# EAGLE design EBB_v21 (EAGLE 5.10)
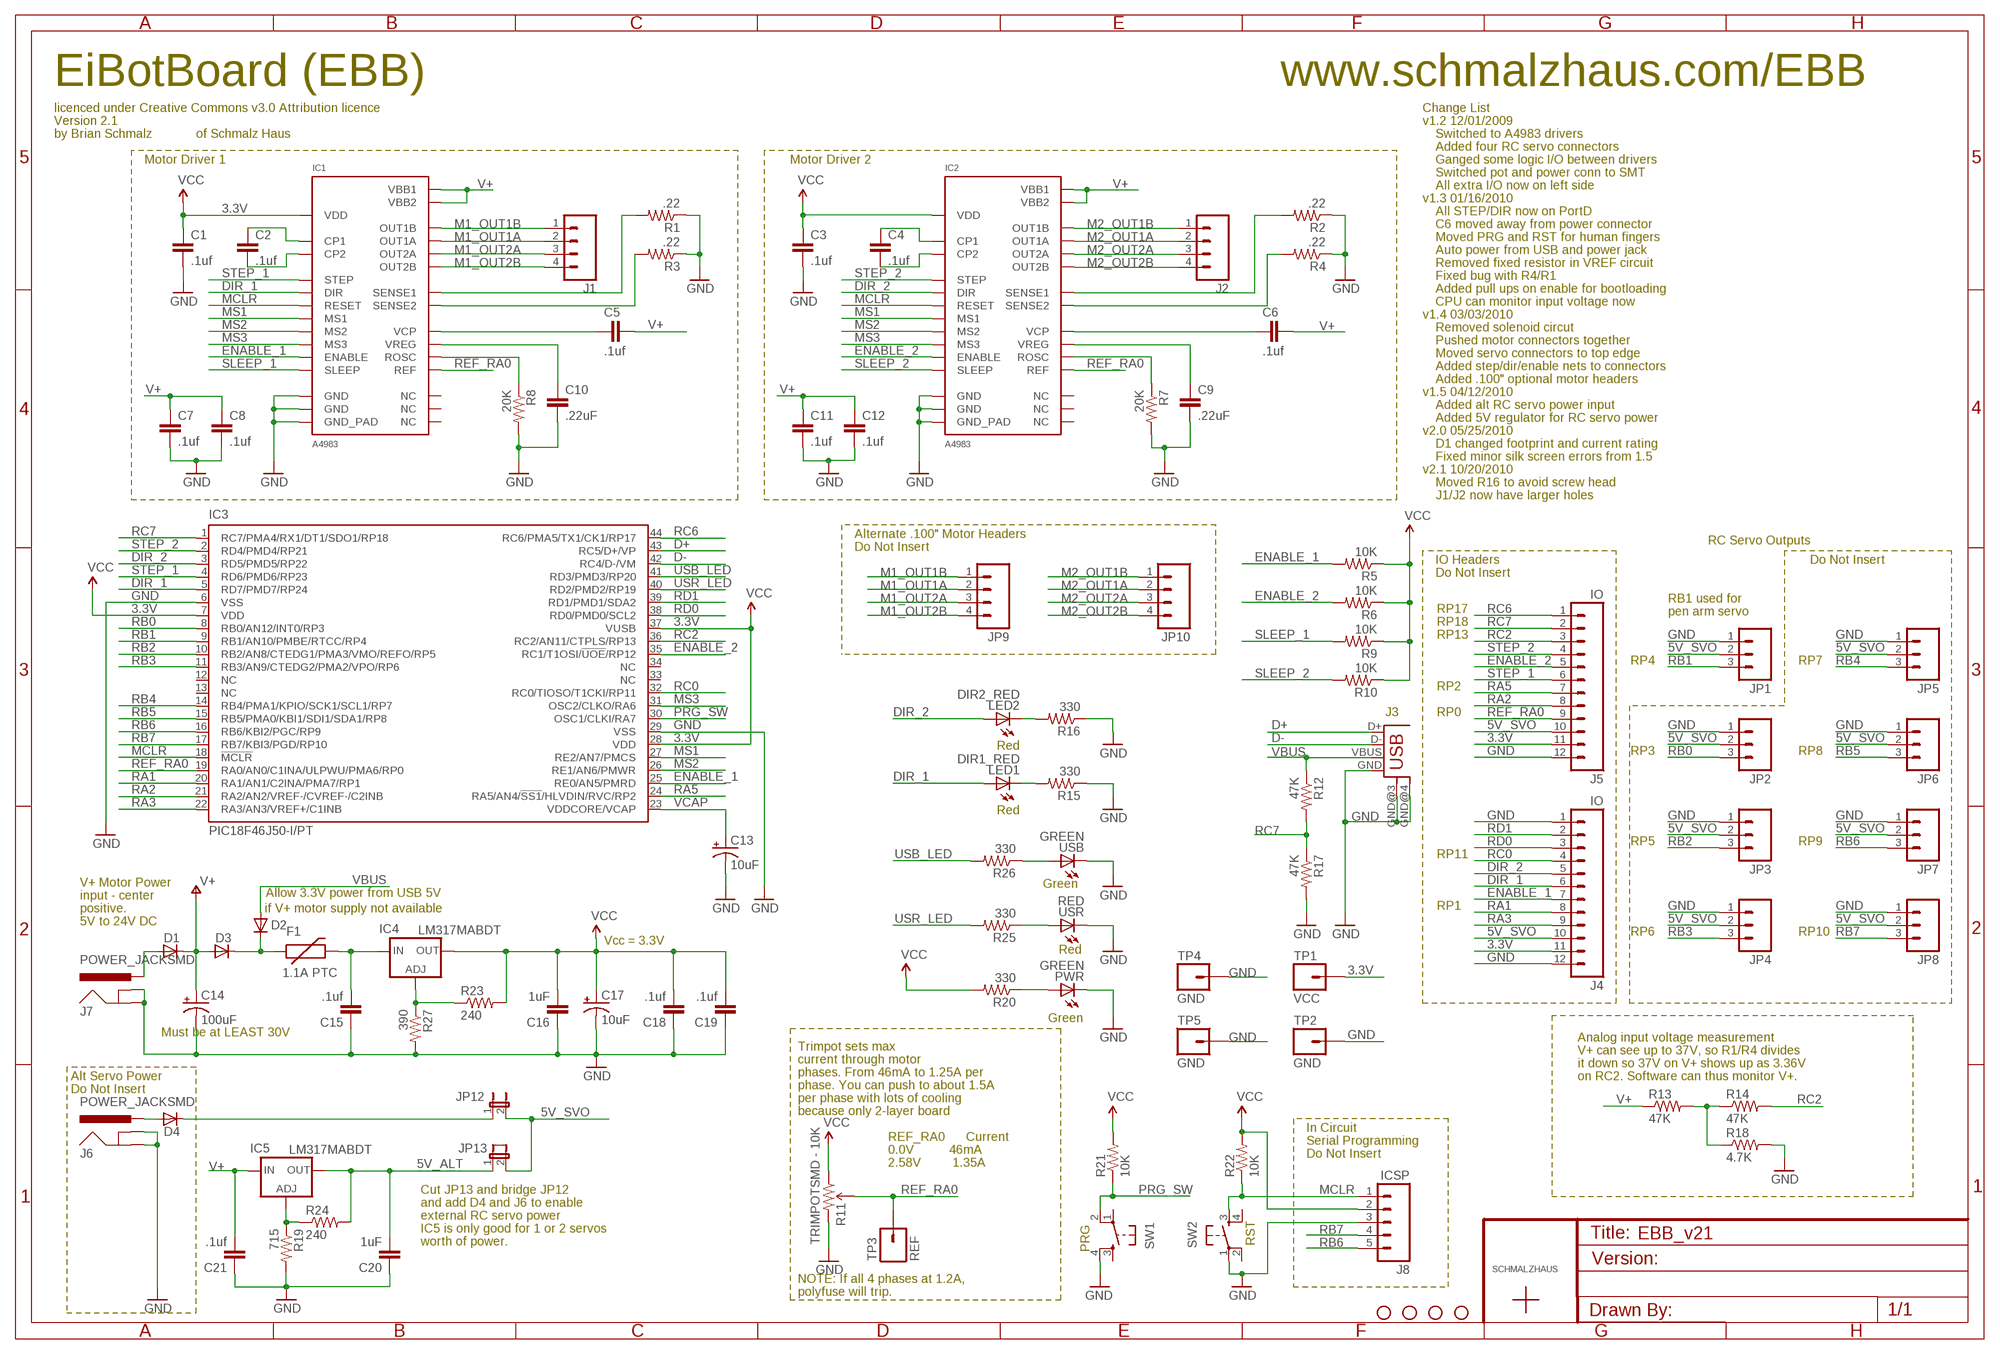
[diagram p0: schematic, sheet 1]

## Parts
C1  .1uf  CAP0603  [0603]
C2  .1uf  CAP0603  [0603]
C3  .1uf  CAP0603  [0603]
C4  .1uf  CAP0603  [0603]
C5  .1uf  CAP0603  [0603]
C6  .1uf  CAP0603  [0603]
C7  .1uf  CAP0603  [0603]
C8  .1uf  CAP0603  [0603]
C9  .22uF  CAP0603  [0603]
C10  .22uF  CAP0603  [0603]
C11  .1uf  CAP0603  [0603]
C12  .1uf  CAP0603  [0603]
C13  10uF  CAP_POL1206  [EIA3216]
C14  100uF  CPOL-USD  [PANASONIC_D]
C15  .1uf  CAP0603  [0603]
C16  1uF  CAP0603  [0603]
C17  10uF  CAP_POL1206  [EIA3216]
C18  .1uf  CAP0603  [0603]
C19  .1uf  CAP0603  [0603]
C20  1uF  CAP0603  [0603]
C21  .1uf  CAP0603  [0603]
D1  DIODE-DO-214AC  [DO-214AC]
D2  CGRM4001-G  [SOD-123_MINI-SMA]
D3  CGRM4001-G  [SOD-123_MINI-SMA]
D4  CGRM4001-G  [SOD-123_MINI-SMA]
F1  1.1A PTC  PTC  [PTC-1812]
IC1  A4983  [QFN28]
IC2  A4983  [QFN28]
IC3  PIC18F46J50-I/PT  PIC18F4J50  [TQFP44]
IC4  LM317MABDT  [DPACK]
IC5  LM317MABDT  [DPACK]
J1  M04SCREW  [SCREWTERMINAL-3.5MM-4]
J2  M04SCREW  [SCREWTERMINAL-3.5MM-4]
J3  USBSMD  [USB-MINIB]
J4  IO  M12PTH  [1X12]
J5  IO  M12PTH  [1X12]
J6  POWER_JACKSMD  [POWER_JACK_SMD]
J7  POWER_JACKSMD  [POWER_JACK_SMD]
J8  ICSP  M05_WIDENOSILK  [1X05_NOSILK]
JP1  M031X03_NO_SILK  [1X03_NO_SILK]
JP2  M031X03_NO_SILK  [1X03_NO_SILK]
JP3  M031X03_NO_SILK  [1X03_NO_SILK]
JP4  M031X03_NO_SILK  [1X03_NO_SILK]
JP5  M031X03_NO_SILK  [1X03_NO_SILK]
JP6  M031X03_NO_SILK  [1X03_NO_SILK]
JP7  M031X03_NO_SILK  [1X03_NO_SILK]
JP8  M031X03_NO_SILK  [1X03_NO_SILK]
JP9  M04POLAR  [MOLEX-1X4]
JP10  M04POLAR  [MOLEX-1X4]
JP12  JUMPER-2SMD-NO  [SJ_2S-NO]
JP13  JUMPER-2SMD-NO  [SJ_2S-NO]
LED1  DIR1_RED  LED0603  [LED-0603]
LED2  DIR2_RED  LED0603  [LED-0603]
PWR  GREEN  LED0603  [LED-0603]
R1  .22  R-US_R0805  [R0805]
R2  .22  R-US_R0805  [R0805]
R3  .22  R-US_R0805  [R0805]
R4  .22  R-US_R0805  [R0805]
R5  10K  R-US_R0603  [R0603]
R6  10K  R-US_R0603  [R0603]
R7  20K  R-US_R0603  [R0603]
R8  20K  R-US_R0603  [R0603]
R9  10K  R-US_R0603  [R0603]
R10  10K  R-US_R0603  [R0603]
R11  TRIMPOTSMD - 10K  TRIMPOTSMD  [TRIMPOT-3MM]
R12  47K  R-US_R0603  [R0603]
R13  47K  R-US_R0603  [R0603]
R14  47K  R-US_R0603  [R0603]
R15  330  R-US_R0603  [R0603]
R16  330  R-US_R0603  [R0603]
R17  47K  R-US_R0603  [R0603]
R18  4.7K  R-US_R0603  [R0603]
R19  715  R-US_R0603  [R0603]
R20  330  R-US_R0603  [R0603]
R21  10K  R-US_R0603  [R0603]
R22  10K  R-US_R0603  [R0603]
R23  240  R-US_R0603  [R0603]
R24  240  R-US_R0603  [R0603]
R25  330  R-US_R0603  [R0603]
R26  330  R-US_R0603  [R0603]
R27  390  R-US_R0603  [R0603]
SW1  PRG  TAC_SWITCHSND  [TACTILE_SWITCH_SMD]
SW2  RST  TAC_SWITCHSND  [TACTILE_SWITCH_SMD]
TP1  VCC  M01_WIDENOSLIK  [1X01_NOSILK]
TP2  GND  M01_WIDENOSLIK  [1X01_NOSILK]
TP3  REF  M01PTH  [1X01]
TP4  GND  M01_WIDENOSLIK  [1X01_NOSILK]
TP5  GND  M01_WIDENOSLIK  [1X01_NOSILK]
U$1  SCHMALZHAUSSCHMALZHAUS_SMALL  [SCHMALZHAUS_SMALL]
U$2  STAND-OFF  [STAND-OFF]
U$3  STAND-OFF  [STAND-OFF]
U$4  STAND-OFF  [STAND-OFF]
U$5  STAND-OFF  [STAND-OFF]
USB  GREEN  LED0603  [LED-0603]
USR  RED  LED0603  [LED-0603]

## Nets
3.3V: C1.1 C3.1 C16.2 C17.A(+) C18.2 C19.2 IC1.P$15(VDD) IC2.P$15(VDD) IC3.7(VDD) IC3.28(VDD) IC3.37(VUSB) IC4.4(OUT) J4.11 J5.11 J8.2 R5.1 R6.1 R9.1 R10.1 R11.1(CCW) R20.2 R21.2 R22.2 R23.2 TP1.1 ; supply symbol labelled VCC
5V_ALT: C20.2 IC5.4(OUT) JP13.1 R24.2
5V_SVO: J4.10 J5.10 JP1.2 JP2.2 JP3.2 JP4.2 JP5.2 JP6.2 JP7.2 JP8.2 JP12.2 JP13.2
D+: IC3.43(RC5/D+/VP) J3.D+
D-: IC3.42(RC4/D-/VM) J3.D-
DIR_1: IC1.P$19(DIR) IC3.5(RD7/PMD7/RP24) J4.6 LED1.A
DIR_2: IC2.P$19(DIR) IC3.3(RD5/PMD5/RP22) J4.5 LED2.A
ENABLE_1: IC1.P$2(ENABLE) IC3.25(RE0/AN5/PMRD) J4.7 R5.2
ENABLE_2: IC2.P$2(ENABLE) IC3.35(RC1/T1OSI/!UOE!/RP12) J5.5 R6.2
GND: C1.2 C3.2 C7.2 C8.2 C9.2 C10.2 C11.2 C12.2 C13.C(-) C14.- C15.1 C16.1 C17.C(-) C18.1 C19.1 C20.1 C21.1 IC1.P$3(GND) IC1.P$18(GND) IC1.P$29(GND_PAD) IC2.P$3(GND) IC2.P$18(GND) IC2.P$29(GND_PAD) IC3.6(VSS) IC3.29(VSS) J3.GND J3.GND@3(GND) J3.GND@4(GND) J4.1 J4.12 J5.12 J6.GND(GNDBREAK) J6.P$4(GND) J7.GND(GNDBREAK) J7.P$4(GND) J8.3 JP1.1 JP2.1 JP3.1 JP4.1 JP5.1 JP6.1 JP7.1 JP8.1 PWR.C R1.1 R2.1 R3.1 R4.1 R7.2 R8.2 R11.3(CW) R15.1 R16.1 R17.2 R18.2 R19.2 R27.2 SW1.4 SW2.1 TP2.1 TP4.1 TP5.1 USB.C USR.C
M1_OUT1A: IC1.P$24(OUT1A) J1.2 JP9.2
M1_OUT1B: IC1.P$21(OUT1B) J1.1 JP9.1
M1_OUT2A: IC1.P$26(OUT2A) J1.3 JP9.3
M1_OUT2B: IC1.P$1(OUT2B) J1.4 JP9.4
M2_OUT1A: IC2.P$24(OUT1A) J2.2 JP10.2
M2_OUT1B: IC2.P$21(OUT1B) J2.1 JP10.1
M2_OUT2A: IC2.P$26(OUT2A) J2.3 JP10.3
M2_OUT2B: IC2.P$1(OUT2B) J2.4 JP10.4
MCLR: IC1.P$12(RESET) IC2.P$12(RESET) IC3.18(!MCLR!) J8.1 R22.1 SW2.3
MS1: IC1.P$9(MS1) IC2.P$9(MS1) IC3.27(RE2/AN7/PMCS)
MS2: IC1.P$10(MS2) IC2.P$10(MS2) IC3.26(RE1/AN6/PMWR)
MS3: IC1.P$11(MS3) IC2.P$11(MS3) IC3.31(OSC2/CLKO/RA6)
N$2: D2.C D3.C F1.1
N$3: C2.1 IC1.P$4(CP1)
N$4: R13.2 R14.1 R18.1
N$5: C2.2 IC1.P$5(CP2)
N$6: D1.A J7.VIN0(PWR)
N$7: D4.A J6.VIN0(PWR)
N$8: IC5.1(ADJ) R19.1 R24.1
N$9: IC4.1(ADJ) R23.1 R27.1
N$10: D4.C JP12.1
N$16: C4.1 IC2.P$4(CP1)
N$17: C4.2 IC2.P$5(CP2)
N$19: IC1.P$13(ROSC) R8.1
N$20: C10.1 IC1.P$8(VREG)
N$21: C5.1 IC1.P$6(VCP)
N$26: LED2.C R16.2
N$27: PWR.A R20.1
N$29: R26.1 USB.A
N$30: R25.1 USR.A
N$31: IC1.P$27(SENSE2) R3.2
N$32: IC1.P$23(SENSE1) R1.2
N$35: LED1.C R15.2
N$36: C15.2 F1.2 IC4.3(IN)
N$41: C6.1 IC2.P$6(VCP)
N$43: IC2.P$23(SENSE1) R2.2
N$44: IC2.P$27(SENSE2) R4.2
N$45: C9.1 IC2.P$8(VREG)
N$48: IC2.P$13(ROSC) R7.1
PRG_SW: IC3.30(OSC1/CLKI/RA7) R21.1 SW1.2
RA1: IC3.20(RA1/AN1/C2INA/PMA7/RP1) J4.8
RA2: IC3.21(RA2/AN2/VREF-/CVREF-/C2INB) J5.8
RA3: IC3.22(RA3/AN3/VREF+/C1INB) J4.9
RA5: IC3.24(RA5/AN4/!SS1!/HLVDIN/RVC/RP2) J5.7
RB0: IC3.8(RB0/AN12/INT0/RP3) JP2.3
RB1: IC3.9(RB1/AN10/PMBE/RTCC/RP4) JP1.3
RB2: IC3.10(RB2/AN8/CTEDG1/PMA3/VMO/REFO/RP5) JP3.3
RB3: IC3.11(RB3/AN9/CTEDG2/PMA2/VPO/RP6) JP4.3
RB4: IC3.14(RB4/PMA1/KPIO/SCK1/SCL1/RP7) JP5.3
RB5: IC3.15(RB5/PMA0/KBI1/SDI1/SDA1/RP8) JP6.3
RB6: IC3.16(RB6/KBI2/PGC/RP9) J8.5 JP7.3
RB7: IC3.17(RB7/KBI3/PGD/RP10) J8.4 JP8.3
RC0: IC3.32(RC0/TIOSO/T1CKI/RP11) J4.4
RC2: IC3.36(RC2/AN11/CTPLS/RP13) J5.3 R14.2
RC6: IC3.44(RC6/PMA5/TX1/CK1/RP17) J5.1
RC7: IC3.1(RC7/PMA4/RX1/DT1/SDO1/RP18) J5.2 R12.2 R17.1
RD0: IC3.38(RD0/PMD0/SCL2) J4.3
RD1: IC3.39(RD1/PMD1/SDA2) J4.2
REF_RA0: IC1.P$17(REF) IC2.P$17(REF) IC3.19(RA0/AN0/C1INA/ULPWU/PMA6/RP0) J5.9 R11.2(WIPER) TP3.1
SLEEP_1: IC1.P$14(SLEEP) R9.2
SLEEP_2: IC2.P$14(SLEEP) R10.2
STEP_1: IC1.P$16(STEP) IC3.4(RD6/PMD6/RP23) J5.6
STEP_2: IC2.P$16(STEP) IC3.2(RD4/PMD4/RP21) J5.4
USB_LED: IC3.41(RD3/PMD3/RP20) R26.2
USR_LED: IC3.40(RD2/PMD2/RP19) R25.2
V+: C5.2 C6.2 C7.1 C8.1 C11.1 C12.1 C14.+ C21.2 D1.C D3.A IC1.P$22(VBB1) IC1.P$28(VBB2) IC2.P$22(VBB1) IC2.P$28(VBB2) IC5.3(IN) R13.1
VBUS: D2.A J3.VBUS R12.1
VCAP: C13.A(+) IC3.23(VDDCORE/VCAP)
Unconnected: IC1.P$7(NC) IC1.P$20(NC) IC1.P$25(NC) IC2.P$7(NC) IC2.P$20(NC) IC2.P$25(NC) IC3.12(NC) IC3.13(NC) IC3.33(NC) IC3.34(NC) SW1.1 SW1.3 SW2.2 SW2.4

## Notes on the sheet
- EiBotBoard (EBB) | www.schmalzhaus.com/EBB
- licenced under Creative Commons v3.0 Attribution licence | Change List
- Version 2.1 | v1.2 12/01/2009
- by Brian Schmalz | of Schmalz Haus | Switched to A4983 drivers
- Added four RC servo connectors
- Motor Driver 1 | Motor Driver 2 | Ganged some logic I/O between drivers
- Switched pot and power conn to SMT
- All extra I/O now on left side
- v1.3 01/16/2010
- All STEP/DIR now on PortD
- C6 moved away from power connector
- Moved PRG and RST for human fingers
- Auto power from USB and power jack
- Removed fixed resistor in VREF circuit
- Fixed bug with R4/R1
- Added pull ups on enable for bootloading
- CPU can monitor input voltage now
- v1.4 03/03/2010
- Removed solenoid circut
- Pushed motor connectors together
- Moved servo connectors to top edge
- Added step/dir/enable nets to connectors
- Added .100" optional motor headers
- v1.5 04/12/2010
- Added alt RC servo power input
- Added 5V regulator for RC servo power
- v2.0 05/25/2010
- D1 changed footprint and current rating
- Fixed minor silk screen errors from 1.5
- v2.1 10/20/2010
- Moved R16 to avoid screw head
- J1/J2 now have larger holes
- Alternate .100" Motor Headers
- RC Servo Outputs
- Do Not Insert
- IO Headers | Do Not Insert
- Do Not Insert
- RB1 used for
- RP17 | pen arm servo
- RP18
- RP13
- RP4 | RP7
- RP2
- J3 | RP0
- Red
- RP3 | RP8
- Red
- RP5 | RP9
- RP11
- V+ Motor Power | Green
- input - center | Allow 3.3V power from USB 5V
- positive. | if V+ motor supply not available | RP1
- 5V to 24V DC
- RP6 | RP10
- Vcc = 3.3V | Red
- Green
- Must be at LEAST 30V
- Analog input voltage measurement
- Trimpot sets max
- V+ can see up to 37V, so R1/R4 divides
- current through motor
- it down so 37V on V+ shows up as 3.36V
- phases. From 46mA to 1.25A per
- Alt Servo Power | on RC2. Software can thus monitor V+.
- phase. You can push to about 1.5A
- Do Not Insert
- per phase with lots of cooling
- because only 2-layer board
- In Circuit
- REF_RA0      Current
- Serial Programming
- 0.0V          46mA
- Do Not Insert
- 2.58V         1.35A
- Cut JP13 and bridge JP12
- and add D4 and J6 to enable
- external RC servo power
- PRG
- IC5 is only good for 1 or 2 servos
- worth of power. | RST
- NOTE: If all 4 phases at 1.2A,
- polyfuse will trip.

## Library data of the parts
C1-C12 C15 C16 C18-C21 = SparkFun-2-11-09:CAP: Capacitor
C13 C17 = SparkFun-2-11-09:CAP_POL: Capacitor Polarized
C14 = rcl:CPOL-US: POLARIZED CAPACITOR, American symbol
D1 = diode:DIODE-: DIODE
D2-D4 = diode:CGRM400*-G: Molded plasitc,JEDEC SOD-123/Mini SMA
F1 = SchmalzHaus:PTC: Resettable Fuse PTC
IC1 IC2 = SchmalzHaus:A4983
IC3 = SchmalzHaus:PIC18F4*J50
IC4 IC5 = v-reg:LM317?*: 500 mA Adjustable Output Positive Voltage Regulator Source: http://www.onsemi.co.jp .. LM317M-D.PDF
J1 J2 = SchmalzHaus:M04: Header 4 Standard 4-pin 0.1" header. Use with straight break away headers (SKU : PRT-00116), right angle break away headers (PRT-00553), swiss pins (PRT-00743), machine pins (PRT-00117), and female headers (PRT-00115). Molex polarized connector foot print use with SKU : PRT-08231 with associated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
J3 = SchmalzHaus:USB: USB Connectors USB-B-PTH is fully proven SKU : PRT-00139 USB-miniB is fully proven SKU : PRT-00587 USB-A-PCB is untested. USB-A-H is throughly reviewed, but untested. Spark Fun Electronics SKU : PRT-00437 USB-B-SMT is throughly reviewed, but untested. Needs silkscreen touching up. USB-A-S has not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
J4 J5 = SparkFun-12-01-09:M12: Header 12 Standard 12-pin 0.1" header. Use with straight break away headers (SKU : PRT-00116), right angle break away headers (PRT-00553), swiss pins (PRT-00743), machine pins (PRT-00117), and female headers (PRT-00115).
J6 J7 = SparkFun11_03_09:POWER_JACK: Power Jack This is the standard 5.5mm barrel jack for power. The PTH is the most common, proven, reliable, footprint. All others are experimental. The Slot footprint only works if the mill layer is transmitted to the PCB fab house so be warned. Spark Fun Electronics SKU : PRT-00119. Mating wall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
J8 = SchmalzHaus:M05_WIDE: Header 5 Standard 5-pin 0.1" header. Use with straight break away headers (SKU : PRT-00116), right angle break away headers (PRT-00553), swiss pins (PRT-00743), machine pins (PRT-00117), and female headers (PRT-00115). Molex polarized connector foot print use with SKU : PRT-08230 with associated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
JP1-JP8 = SparkFun-12-01-09:M03: Header 3 Standard 3-pin 0.1" header. Use with straight break away headers (SKU : PRT-00116), right angle break away headers (PRT-00553), swiss pins (PRT-00743), machine pins (PRT-00117), and female headers (PRT-00115). Molex polarized connector foot print use with SKU : PRT-08232 with associated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
JP9 JP10 = SparkFun-12-01-09:M04: Header 4 Standard 4-pin 0.1" header. Use with straight break away headers (SKU : PRT-00116), right angle break away headers (PRT-00553), swiss pins (PRT-00743), machine pins (PRT-00117), and female headers (PRT-00115). Molex polarized connector foot print use with SKU : PRT-08231 with associated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
JP12 JP13 = SparkFun-12-01-09:JUMPER-2: Jumper
LED1 LED2 PWR USB USR = SparkFun-2-11-09:LED: LEDs
R1-R10 R12-R27 = rcl:R-US_: RESISTOR, American symbol
R11 = SparkFun11_03_09:TRIMPOT
SW1 SW2 = SparkFunEagle-6-6-07:TAC_SWITCH: Momentary Switch Button commonly used for reset or general input. Spark Fun Electronics SKU : COM-00097
TP1 TP2 TP4 TP5 = SchmalzHaus:M01_WIDE: Header 1
TP3 = SchmalzHaus:M01: Header 1
U$1 = SchmalzHaus:SCHMALZHAUS
U$2-U$5 = SparkFun01082009:STAND-OFF: Stand Off

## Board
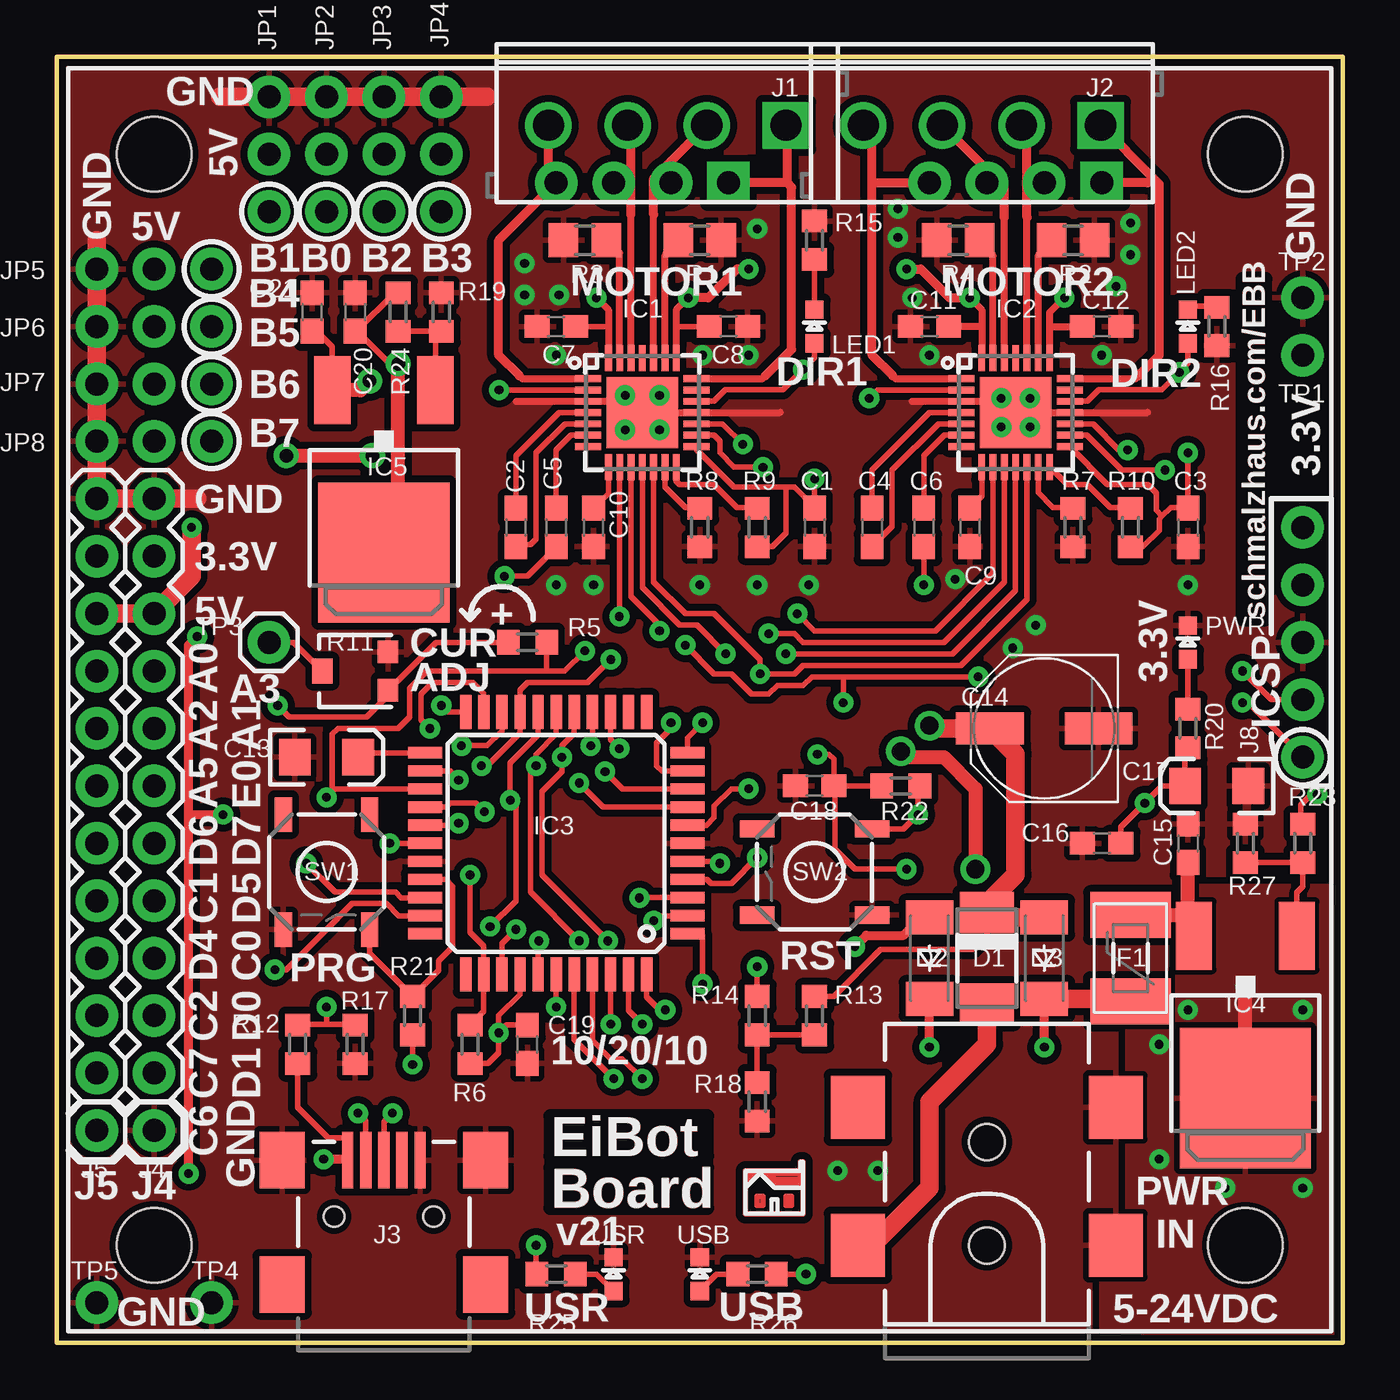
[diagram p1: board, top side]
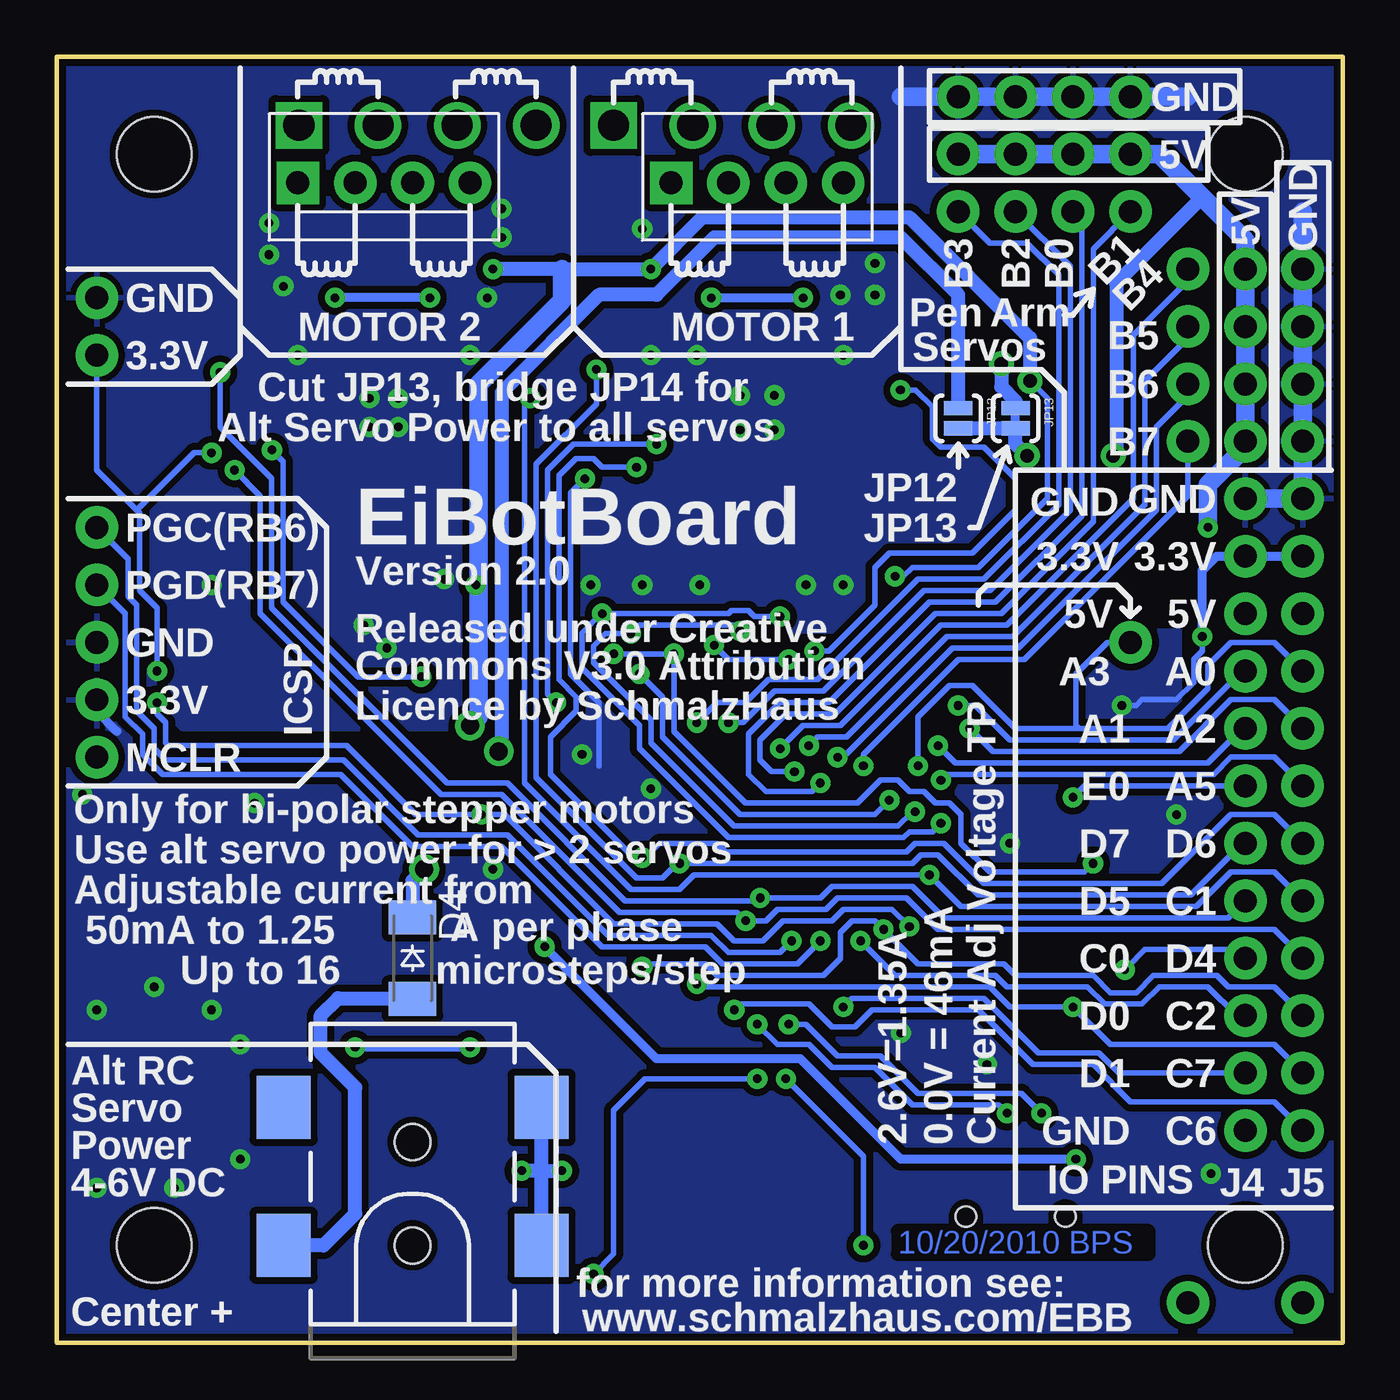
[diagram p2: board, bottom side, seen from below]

Size 56.9 x 56.9 mm. Coordinates in mm from the lower left corner, seen from the top.
Outline: 0,56.9 0,0 56.9,0 56.9,56.9 0,56.9
Copper layers (1*16): Top 0.035mm / dielectric 1.5mm / Bottom 0.035mm
Design rules "GoldPhoenix_8and8": minimum track width 7mil, minimum drill 15mil, track to track 8mil, track to pad 8mil, pad to pad 8mil, via to via 8mil, smd to smd 8mil, copper to edge 10mil, drill to drill 8mil, minimum pad ring 12mil, minimum via ring 10mil, stop-mask expansion 4mil, vias tented up to drill 25mil, thermal gap 10mil

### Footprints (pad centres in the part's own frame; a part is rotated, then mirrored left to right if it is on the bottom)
0603 = smd 1.1 x 1: 1 -0.85,0; 2 0.85,0
EIA3216 = smd 1.4 x 1.6: A 1.4,0; C -1.4,0
PANASONIC_D = smd 3 x 1.4: + 2.4,0; - -2.4,0
DO-214AC = smd 1.8 x 2.4: A 2.025,0; C -2.025,0
SOD-123_MINI-SMA = smd 1.5 x 2.1: A 1.8,0; C -1.8,0
PTC-1812 = smd 2.032 x 3.556: 1 -1.905,0; 2 1.905,0
QFN28 = smd 1.15 x 0.3: P$1 -2.4,1.5; P$2 -2.4,1; P$3 -2.4,0.5; P$4 -2.4,0; P$5 -2.4,-0.5; P$6 -2.4,-1; P$7 -2.4,-1.5; P$15 2.4,-1.5; P$16 2.4,-1; P$17 2.4,-0.5; P$18 2.4,0; P$19 2.4,0.5; P$20 2.4,1; P$21 2.4,1.5 | smd 0.3 x 1.15: P$8 -1.5,-2.4; P$9 -1,-2.4; P$10 -0.5,-2.4; P$11 0,-2.4; P$12 0.5,-2.4; P$13 1,-2.4; P$14 1.5,-2.4; P$22 1.5,2.4; P$23 1,2.4; P$24 0.5,2.4; P$25 0,2.4; P$26 -0.5,2.4; P$27 -1,2.4; P$28 -1.5,2.4 | smd 3.15 x 3.15: P$29 0,0
TQFP44 = smd 1.5 x 0.5: 1 -5.8,4; 2 -5.8,3.2; 3 -5.8,2.4; 4 -5.8,1.6; 5 -5.8,0.8; 6 -5.8,0; 7 -5.8,-0.8; 8 -5.8,-1.6; 9 -5.8,-2.4; 10 -5.8,-3.2; 11 -5.8,-4; 23 5.8,-4; 24 5.8,-3.2; 25 5.8,-2.4; 26 5.8,-1.6; 27 5.8,-0.8; 28 5.8,0; 29 5.8,0.8; 30 5.8,1.6; 31 5.8,2.4; 32 5.8,3.2; 33 5.8,4 | smd 0.5 x 1.5: 12 -4,-5.8; 13 -3.2,-5.8; 14 -2.4,-5.8; 15 -1.6,-5.8; 16 -0.8,-5.8; 17 0,-5.8; 18 0.8,-5.8; 19 1.6,-5.8; 20 2.4,-5.8; 21 3.2,-5.8; 22 4,-5.8; 34 4,5.8; 35 3.2,5.8; 36 2.4,5.8; 37 1.6,5.8; 38 0.8,5.8; 39 0,5.8; 40 -0.8,5.8; 41 -1.6,5.8; 42 -2.4,5.8; 43 -3.2,5.8; 44 -4,5.8
DPACK = smd 1.6 x 3: 1 -2.28,-4.8; 3 2.28,-4.8 | smd 5.8 x 6.2: 4 0,2.38
SCREWTERMINAL-3.5MM-4 = drill 1.372 square: 1 0,0 | drill 1.372 round: 2 3.5,0; 3 7,0; 4 10.5,0
USB-MINIB = smd 2.5 x 0.5: D+ 2.5,0; D- 2.5,0.8; GND 2.5,-1.6; ID 2.5,-0.8; VBUS 2.5,1.6 | smd 2.5 x 2: GND@1 -3,-4.5; GND@2 -3,4.5; GND@3 2.5,4.5; GND@4 2.5,-4.5 | hole 0.9: 0,2.2; 0,-2.2
1X12 = drill 1.016 pad 1.88 round: 1 0,0; 2 2.54,0; 3 5.08,0; 4 7.62,0; 5 10.16,0; 6 12.7,0; 7 15.24,0; 8 17.78,0; 9 20.32,0; 10 22.86,0; 11 25.4,0; 12 27.94,0
POWER_JACK_SMD = smd 2.8 x 2.4: GND 0,-5.7; P$4 6.1,-5.7; VIN0 0,5.7; VIN1 6.1,5.7 | hole 1.6: 0,0; 4.572,0
1X05_NOSILK = drill 1.016 pad 1.88 round: 1 0,0; 2 2.54,0; 3 5.08,0; 4 7.62,0; 5 10.16,0
1X03_NO_SILK = drill 1.016 pad 1.88 round: 1 0,0; 2 2.54,0; 3 5.08,0
MOLEX-1X4 = drill 1.016 pad 1.88 square: 1 0,0 | drill 1.016 pad 1.88 round: 2 2.54,0; 3 5.08,0; 4 7.62,0
SJ_2S-NO = smd 0.635 x 1.27: 1 -0.45,0; 2 0.45,0
LED-0603 = smd 0.8 x 0.8: A 0,-0.75; C 0,0.75
R0805 = smd 1.3 x 1.5: 1 -0.95,0; 2 0.95,0
R0603 = smd 1 x 1.1: 1 -0.85,0; 2 0.85,0
TRIMPOT-3MM = smd 1 x 0.9: 1 -0.85,-1.45; 3 0.85,-1.45 | smd 1.1 x 0.9: 2 0,1.45
TACTILE_SWITCH_SMD = smd 1.524 x 0.762: 1 -2.54,1.905; 2 2.54,1.905; 3 -2.54,-1.905; 4 2.54,-1.905
1X01_NOSILK = drill 1.016 pad 1.88 round: 1 0,0
1X01 = drill 1.016 pad 1.88 round: 1 0,0
STAND-OFF = hole 3.302: 0,0

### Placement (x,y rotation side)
C1  33.53,36.07 270 top
C2  20.32,36.07 270 top
C3  50.04,36.07 270 top
C4  36.07,36.07 270 top
C5  22.1,36.07 270 top
C6  38.35,36.07 270 top
C7  22.1,44.96 180 top
C8  29.72,44.96 0 top
C9  40.39,36.07 270 top
C10  23.75,36.07 270 top
C11  38.61,44.96 180 top
C12  46.23,44.96 0 top
C13  11.94,25.91 0 top
C14  43.69,27.18 180 top
C15  50.04,22.1 270 top
C16  46.23,22.1 0 top
C17  51.31,24.64 180 top
C18  33.53,24.64 0 top
C19  20.83,13.21 90 top
C20  13.21,45.59 270 top
C21  11.3,45.59 270 top
D1  41.15,17.02 270 top
D2  38.61,17.02 90 top
D3  43.69,17.02 90 top
D4  41.15,17.02 270 bottom
F1  47.5,17.02 90 top
IC1  25.91,41.15 0 top
IC2  42.42,41.15 0 top
IC3  22.1,22.1 180 top
IC4  52.58,13.21 180 top
IC5  14.48,37.34 180 top
J1  32.26,53.85 180 top
J2  46.18,53.85 180 top
J3  14.48,5.59 90 top
J4  4.32,9.4 90 top
J5  1.78,9.4 90 top
J6  41.15,4.32 90 bottom
J7  41.15,4.32 90 top
J8  55.12,25.91 90 top
JP1  9.4,55.12 270 top
JP2  11.94,55.12 270 top
JP3  14.48,55.12 270 top
JP4  17.02,55.12 270 top
JP5  1.78,47.5 0 top
JP6  1.78,44.96 0 top
JP7  1.78,42.42 0 top
JP8  1.78,39.88 0 top
JP9  29.72,51.31 0 bottom
JP10  46.23,51.31 0 bottom
JP12  17.02,40.89 270 bottom
JP13  14.48,40.89 270 bottom
LED1  33.53,44.96 0 top
LED2  50.04,44.96 0 top
PWR  50.04,30.99 0 top
R1  28.45,48.77 180 top
R2  44.96,48.77 180 top
R3  23.37,48.77 0 top
R4  39.88,48.77 0 top
R5  20.83,30.99 0 top
R6  18.29,13.21 90 top
R7  44.96,36.07 270 top
R8  28.45,36.07 270 top
R9  30.99,36.07 90 top
R10  47.5,36.07 90 top
R11  13.21,29.72 90 top
R12  10.67,13.21 90 top
R13  33.53,14.48 270 top
R14  30.99,14.48 90 top
R15  33.53,48.77 270 top
R16  51.31,44.96 90 top
R17  13.21,13.21 270 top
R18  30.99,10.67 270 top
R19  17.02,45.59 90 top
R20  50.04,27.18 270 top
R21  15.75,14.48 270 top
R22  37.34,24.64 180 top
R23  55.12,22.1 90 top
R24  15.11,45.59 90 top
R25  22.1,3.05 180 top
R26  30.99,3.05 0 top
R27  52.58,22.1 90 top
SW1  11.94,20.83 270 top
SW2  33.53,20.83 180 top
TP1  55.12,43.69 0 top
TP2  55.12,46.23 0 top
TP3  9.4,30.99 0 top
TP4  6.86,1.78 0 top
TP5  1.78,1.78 0 top
U$1  31.75,5.71 0 top
U$2  52.58,4.32 0 top
U$3  4.32,4.32 0 top
U$4  52.58,52.58 0 top
U$5  4.32,52.58 0 top
USB  28.45,3.05 0 top
USR  24.64,3.05 0 top

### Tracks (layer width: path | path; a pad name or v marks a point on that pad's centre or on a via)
3.3V  (via drill 0.38)
  Top 0.254: IC1.P$15 28.31,39.51 29.97,37.85 32.26,37.85 | 32.26,37.85 32.64,37.85 33.53,36.96 C1.1 v33.53,38.23 | 50,36.96 49.28,36.96 48.9,36.58 | IC3.37 20.5,15.42 19.56,14.48 v19.56,13.72 | R10.1 48.05,35.22 48.77,35.94 48.77,36.45 48.9,36.58 | R9.1 31.66,35.22 32.26,35.81 32.26,37.85 | C3.1 v50.04,39.37 | R21.2 v15.75,12.32 15.79,12.36 | v19.56,13.72 19.9,14.06 C19.2 | R6.1 19.09,12.36 19.56,12.83 v19.56,13.72 | v37.59,20.95 35.31,20.95 34.42,21.84 34.42,24.6 C18.2 | IC3.7 28.74,22.9 29.08,23.24 29.08,23.75 29.84,24.51 v30.61,24.51 | v14.73,22.1 IC3.28 | R23.2 55.03,22.95 55.03,23.79 55.5,24.26 v55.75,24.26 | v52.45,29.72 53.72,28.45 J8.2 | C16.2 47.08,22.82 v48.13,23.88 48.9,24.64 C17.A 49.91,26.2 R20.2 | C18.2 R22.2 | C18.2 34.38,25.82 34.16,26.04 v33.66,26.04 | 48.9,36.58 48.64,36.83 48.64,37.59 48.26,37.97 46.48,37.97 44.82,39.64 IC2.P$15 | R5.1 16.78,30.99 R11.1 14.66,28.63 13.72,27.69 10.29,27.69 v9.78,28.19
  Top 0.305: 50,36.96 C3.1
  Top 0.406: v5.84,7.49 5.84,23.37 | 5.84,23.37 v7.37,23.37 | 5.84,23.37 5.84,30.86 v6.22,31.24
  Top 0.61: IC4.4 v52.58,15.75
  Bottom 0.254: v33.53,38.23 34.16,37.59 34.16,29.59 32.89,28.32 32.89,25.53 | v52.45,29.72 52.45,32.51 53.21,33.27 53.21,36.7 53.34,36.83 | 53.34,36.83 55.12,38.61 TP1.1 | v50.04,39.37 50.8,39.37 53.34,36.83 | 6.22,34.16 6.22,32.51 | v6.22,31.24 6.22,30.61 6.6,30.23 6.6,29.21 7.37,28.45 8.89,28.45 9.14,28.19 v9.78,28.19
  Bottom 0.406: J5.11 J4.11 5.59,34.8 6.22,34.16 v6.22,31.24 | J8.2 55.12,27.94 54.23,27.05
  other vias: 48.77,13.21 48.77,8.13 55.12,6.86 51.69,6.86 55.12,14.73 50.04,14.73
  pour Bottom (isolate 0.305, rank 3): 0.25,28.45 0.25,0.25 56.64,0.25 56.64,29.72 52.58,29.72 52.58,25.91 39.88,25.91 33.53,31.5 7.24,31.5 7.24,28.45
  pour Top: 47.37,15.11 47.37,4.95 46.23,3.68 46.23,0.51 56.64,0.25 56.39,20.19 49.53,20.19 49.53,15.11
5V_ALT  (via drill 0.6)
  Top 0.254: 15.04,46.44 R24.2 15.11,46.48 14.99,46.48 13.25,44.74 C20.2 13.42,44.74 13.42,44.62 14.73,43.31 v15.11,43.31
  Top 0.61: IC5.4 14.48,37.21 15.11,37.85 v15.11,43.31
  Bottom 0.61: v15.11,43.31 15.11,42.29 14.48,41.66 JP13.1
5V_SVO  (via drill 0.38, 0.6)
  Top 0.61: v10.16,39.24 v13.97,39.24
  Top 0.813: v5.97,36.07 5.97,33.91 J4.10 J5.10
  Bottom 0.406: 4.32,39.62 JP8.2 | 6.86,51.31 6.86,51.18 6.22,50.55 6.35,50.55
  Bottom 0.61: JP12.2 JP13.2 14.48,39.75 v13.97,39.24 | 6.35,50.55 10.03,46.86 10.03,39.37 v10.16,39.24
  Bottom 0.813: JP4.2 JP3.2 JP2.2 JP1.2 8.13,52.58 6.86,51.31 4.32,48.77 JP5.2 JP6.2 JP7.2 JP8.2 | 4.32,39.62 5.97,37.97 v5.97,36.07
D+  (via drill 0.38)
  Top 0.254: IC3.43 25.3,14.71 v25.91,14.1 | J3.D+ 14.48,9.78 v14.86,10.16
  Bottom 0.254: v25.91,14.1 25.02,13.21 23.62,13.21 22.61,12.19 20.7,12.19 19.05,10.54 15.24,10.54 v14.86,10.16
D-  (via drill 0.38)
  Top 0.254: 13.72,8.05 J3.D- 13.68,9.82 v13.34,10.16 | IC3.42 24.5,14.11 v24.51,14.1
  Bottom 0.254: v24.51,14.1 23.75,14.1 22.35,12.7 20.45,12.7 18.8,11.05 14.22,11.05 v13.34,10.16
DIR_1  (via drill 0.38)
  Top 0.254: LED1.A 33.53,43.57 v33.02,43.07 v33.02,43.05 32.13,42.16 29.59,42.16 29.07,41.65 IC1.P$19 | IC3.5 29.3,21.3 29.3,21.25 v29.34,21.21
  Bottom 0.254: J4.6 4.45,22.1 6.73,19.81 16.13,19.81 17.91,21.59 18.67,21.59 19.05,21.21 v29.34,21.21 29.46,21.21 30.1,20.57 31.24,20.57 35.69,25.02 35.69,38.86 33.02,41.53 v33.02,43.05
DIR_2  (via drill 0.38)
  Top 0.254: IC3.3 25.79,19.7 v25.78,19.68 | 48.9,42.16 48.89,42.16 | 48.9,42.16 46.1,42.16 45.59,41.65 IC2.P$19 | 48.9,42.16 v49.66,42.93 50.04,43.31 50.03,43.31 50.03,44.2 LED2.A
  Bottom 0.254: v49.66,42.93 49.66,40.51 47.37,38.23 47.37,32.51 39.62,24.77 36.96,24.77 31.75,19.56 25.91,19.56 v25.78,19.68 23.11,19.68 22.61,20.19 19.05,20.19 17.65,18.8 5.08,18.8 J4.5
ENABLE_1  (via drill 0.38)
  Top 0.254: v19.57,42.15 IC1.P$2 | IC3.25 15.25,24.5 15.24,24.51 12.32,24.51 12.19,24.38 | v11.94,24.13 12.19,24.38 | 12.19,24.38 12.19,26.92 12.45,27.18 15.11,27.18 15.62,27.69 15.62,28.96 16.38,29.72 21.72,29.72 | 21.72,29.72 22.48,29.72 v23.37,30.61 | R5.2 21.68,29.76 21.72,29.72
  Bottom 0.254: J4.7 11.43,24.64 v11.94,24.13 | v23.37,30.61 22.73,30.61 20.7,32.64 20.7,34.29 20.07,34.93 16.38,34.93 14.48,36.83 14.48,38.23 15.88,39.62 17.78,39.62 18.16,40.01 18.16,41.4 18.91,42.15 v19.57,42.15
ENABLE_2  (via drill 0.38)
  Top 0.254: R6.2 18.9,14.67 IC3.35 18.9,17.55 18.29,18.16 v18.29,20.7 | IC2.P$2 36.31,42.15 v35.94,41.78
  Bottom 0.254: J5.5 3.05,20.83 4.95,20.83 6.48,19.3 16.89,19.3 v18.29,20.7 28.7,20.7 29.34,20.07 31.5,20.07 36.2,24.77 36.2,41.53 v35.94,41.78
GND  (via drill 0.38)
  Top 0.254: v26.67,40.39 26.67,40.77 27.05,41.15 | v41.78,41.78 IC2.P$29 | J4.12 4.45,37.34 | v25.15,41.91 25.02,41.91 24.76,41.65
  Top 0.305: 20.33,41.65 IC1.P$3 24.76,41.65 24.77,41.66 | 27.05,41.15 IC1.P$18 32,41.15 | 41.66,41.66 41.65,41.65 IC2.P$3 37.85,41.65 37.85,41.66 | IC2.P$29 IC2.P$18 48.26,41.15
  Top 0.406: 41.65,41.65 v41.78,41.78
  Top 0.813: 1.78,48.77 JP8.1 J5.12 J4.12 6.22,37.34 | 7.24,55.12 19.05,55.12
  Bottom 0.254: 36.34,7.61 v36.32,7.62 | 34.56,7.61 v34.54,7.62
  Bottom 0.61: J6.GND 35.45,7.61 | 35.45,7.61 J6.P$4 | 35.45,7.61 36.34,7.61 | 35.45,7.61 34.56,7.61
  Bottom 0.813: 1.78,50.04 JP8.1 J5.12 J4.12 | 6.86,55.12 19.56,55.12
  other vias: 20.7,46.36 22.1,43.69 28.57,43.69 30.61,43.69 30.99,49.28 20.7,47.75 22.22,46.36 26.67,41.91 25.15,40.39 28.45,33.53 30.99,33.53 33.27,33.53 23.75,33.53 43.05,41.78 43.05,40.51 41.78,40.51 37.85,46.23 38.61,43.69 46.23,43.69 47.5,49.53 47.5,48.13 37.21,48.9 37.21,50.16 39.75,33.78 42.29,30.73 50.04,33.53 43.31,31.75 22.1,33.53 46.86,46.74
  pour Top (isolate 0.305, rank 3): 0.25,56.64 0.25,0.25 56.64,0.25 56.64,56.64
  pour Bottom (isolate 0.305, rank 2): 0.25,28.45 0.25,56.64 56.64,56.64 56.64,29.72 52.58,29.72 52.58,28.45 51.31,27.18 33.53,27.18 33.53,31.5 7.24,31.5 7.24,28.45
M1_OUT1A
  Top 0.305: IC1.P$24 26.41,49.9
  Top 0.406: 26.41,49.9 26.41,51.18 | 26.41,51.18 26.41,51.5 J1.2 | JP9.2 26.54,51.31 26.41,51.18
M1_OUT1B
  Top 0.254: 31.22,42.65 31.24,42.67
  Top 0.305: 31.24,42.67 31.34,42.78 | IC1.P$21 31.22,42.65
  Top 0.406: 31.34,42.78 32.51,43.94 32.51,51.11 32.32,51.31 | 32.32,51.31 32.32,53.79 J1.1 | 32.32,51.31 JP9.1
M1_OUT2A
  Top 0.305: IC1.P$26 25.41,49.9
  Top 0.406: 25.41,49.9 25.41,51.31 | 25.41,51.31 25.41,53.7 J1.3 | 25.41,51.31 JP9.3
M1_OUT2B
  Top 0.305: 20.47,42.78 20.57,42.67 20.6,42.65 IC1.P$1
  Top 0.406: 20.47,42.78 19.56,43.69 19.56,48.77 JP9.4 21.76,51.65 J1.4
M2_OUT1A
  Top 0.305: IC2.P$24 42.92,49.78
  Top 0.406: 42.92,49.78 42.92,51.31 | 42.92,51.31 42.92,53.61 J2.2 | 42.92,51.31 JP10.2
M2_OUT1B
  Top 0.254: 47.73,42.65 47.75,42.67
  Top 0.305: 47.75,42.67 47.86,42.78 | IC2.P$21 47.73,42.65
  Top 0.406: 47.86,42.78 48.77,43.69 48.77,51.26 48.49,51.54 | 48.49,51.54 J2.1 | JP10.1 48.26,51.31 48.49,51.54
M2_OUT2A
  Top 0.305: IC2.P$26 41.92,49.78
  Top 0.406: 41.92,49.78 41.92,51.11 41.5,51.53 | 41.5,51.53 J2.3 | JP10.3 41.28,51.31 41.5,51.53
M2_OUT2B
  Top 0.305: IC2.P$1 37.11,42.65 36.98,42.78
  Top 0.406: 36.98,42.78 36.07,43.69 36.07,51.31 | 36.07,51.31 36.07,53.46 J2.4 | 36.07,51.31 JP10.4
MCLR  (via drill 0.38)
  Top 0.254: IC1.P$12 26.41,33.65 26.42,33.64 26.43,33.64 27.81,32.26 29.08,32.26 31.11,30.23 v31.11,29.59 32.64,29.59 33.02,29.97 40.01,29.97 42.92,32.89 IC2.P$12 | v19.18,18.41 20.32,19.56 20.32,23.75 v20.07,24 20.07,25.65 21.3,26.89 IC3.18 | v52.45,28.32 52.71,28.32 J8.1 | R22.1 38.1,24.55 v38.1,23.37 37.47,22.73 SW2.3
  Bottom 0.254: v52.45,28.32 52.45,27.81 52.07,27.43 52.07,26.54 51.94,26.42 44.07,26.42 41.02,23.37 v38.1,23.37 37.08,23.37 32.26,18.54 27.69,18.54 26.92,17.78 25.65,17.78 24.77,18.67 22.61,18.67 22.1,19.18 19.94,19.18 v19.18,18.41 | v31.11,29.59 30.1,28.57 30.1,26.8 26.67,23.37 20.7,23.37 v20.07,24
MS1  (via drill 0.38)
  Top 0.254: IC1.P$9 24.91,33.04 24.89,33.02 v24.89,32.13 | v32.77,32.26 33.53,31.5 38.86,31.5 41.42,34.05 IC2.P$9 | IC3.27 17.31,22.9 17.4,22.99 v17.78,22.99
  Bottom 0.254: v24.89,32.13 26.04,32.13 26.29,32.38 27.05,32.38 27.18,32.26 v32.77,32.26 32.8,32.26 33.66,31.41 33.66,29.84 31.11,27.3 31.11,26.29 27.18,22.35 19.43,22.35 19.18,22.61 18.16,22.61 v17.78,22.99
MS2  (via drill 0.38)
  Top 0.254: IC1.P$10 25.41,33.03 25.4,33.02 26.67,31.75 v26.67,31.5 | v31.5,31.37 32.64,31.37 33.02,30.99 39.24,30.99 41.92,33.66 IC2.P$10 | IC3.26 17.22,23.7 17.4,23.88 18.54,23.88 v18.92,23.49
  Bottom 0.254: v18.92,23.49 19.05,23.49 19.68,22.86 26.92,22.86 30.61,26.54 30.61,27.56 33.15,30.1 33.15,30.83 32.61,31.37 v31.5,31.37 31.11,31.75 26.92,31.75 v26.67,31.5
MS3  (via drill 0.38)
  Top 0.254: IC1.P$11 25.91,33.4 27.56,31.75 28.32,31.75 v29.59,30.48 | v32.26,30.48 39.62,30.48 42.42,33.27 IC2.P$11 | IC3.31 16.31,19.68 15.24,19.68 14.99,19.94 12.32,19.94 v11.05,21.21
  Bottom 0.254: v32.26,30.48 v29.59,30.48 29.59,27.05 26.42,23.88 21.46,23.88 20.45,24.89 19.68,24.89 19.18,24.38 18.54,24.38 18.03,23.88 17.4,23.88 16.89,23.37 16.89,22.1 15.62,20.83 11.43,20.83 v11.05,21.21
N$1
  Bottom 0.406: 14.48,40.26 14.48,41.53
N$2  (via drill 0.38)
  Top 0.406: 47.39,15.22 F1.1 | v43.69,13.08 D3.C | v38.61,13.08 D2.C
  Top 0.813: D3.C 47.39,15.22
  Bottom 0.406: v38.61,13.08 v43.69,13.08
N$3
  Top 0.254: C2.1 20.32,39.24 22.22,41.15 IC1.P$4
N$4
  Top 0.254: R13.2 R14.1 R18.1
N$5
  Top 0.254: IC1.P$5 22.49,40.65 21.21,39.37 21.21,35.56 20.95,35.31 20.41,35.31 C2.2
N$6
  Top 0.406: J7.VIN0 36.07,4.32
  Top 0.813: 36.07,4.32 38.61,6.86 38.61,10.67 41.15,13.21 D1.A
N$7
  Bottom 0.406: 41.17,15.24 D4.A
  Bottom 0.61: J6.VIN0 45.09,4.32 43.69,5.71 43.69,11.3 45.21,12.83 45.21,14.48 44.45,15.24 41.17,15.24
N$8
  Top 0.254: R24.1 R19.1 16.76,44.74 | IC5.1 16.76,44.7 16.76,44.74 | 16.76,44.74 16.76,45.12
N$9
  Top 0.254: R27.1 R23.1 55.12,20.19 54.86,19.93 IC4.1
N$10  (via drill 0.8)
  Top 0.61: v40.64,20.95 40.64,24.51 39.24,25.91 37.59,25.91 v37.34,26.16
  Bottom 0.254: 41.15,19.3 D4.C
  Bottom 0.61: 41.15,19.3 41.15,20.45 v40.64,20.95 | v37.34,26.16 37.21,26.29 37.21,42.04 32.89,46.36 30.35,46.36 27.81,48.9 19.56,48.9 17.02,46.36 JP12.1
N$16
  Top 0.254: IC2.P$4 38.61,41.15 36.07,38.61 C4.1
N$17
  Top 0.254: IC2.P$5 39,40.65 36.96,38.61 36.96,36.11 C4.2
N$19
  Top 0.254: IC1.P$13 26.91,37.86 27.81,36.96 28.41,36.96
  Top 0.305: 28.41,36.96 R8.1
N$20
  Top 0.254: IC1.P$8 24.41,37.58 C10.1
N$21
  Top 0.254: IC1.P$6 22.75,40.15 22.1,39.5 C5.1
N$26
  Top 0.254: LED2.C 50.04,45.85 51.31,45.85 R16.2
N$27
  Top 0.254: R20.1 PWR.A
N$29
  Top 0.254: R26.1 29.2,3.05 USB.A
N$30
  Top 0.254: R25.1 23.89,3.05 USR.A
N$31
  Top 0.254: 24.91,48.21 24.78,48.21 24.78,48.3 R3.2
  Top 0.305: IC1.P$27 24.91,48.21
N$32
  Top 0.254: 26.91,48.08 26.91,48.18 R1.2
  Top 0.305: IC1.P$23 26.91,48.08
N$35
  Top 0.254: 33.55,45.71 LED1.C R15.2
N$36
  Top 0.254: 49.78,18.92 49.78,18.52 IC4.3
  Top 0.61: C15.2 50.04,19.18 49.78,18.92 F1.2
N$41
  Top 0.254: IC2.P$6 39.26,40.15 38.35,39.24 C6.1
N$43
  Top 0.254: 43.42,48.08 43.42,48.18 R2.2
  Top 0.305: IC2.P$23 43.42,48.08
N$44
  Top 0.254: 41.42,48.08 41.42,48.18 R4.2
  Top 0.305: IC2.P$27 41.42,48.08
N$45
  Top 0.254: IC2.P$8 40.92,37.45 C9.1
N$48
  Top 0.254: IC2.P$13 43.42,37.61 44.07,36.96 44.92,36.96
  Top 0.305: 44.92,36.96 R7.1
PRG_SW
  Top 0.254: SW1.2 13.84,17.23 R21.1 16.89,16.47 16.89,16.89 17.53,17.53 17.53,20.19 17.22,20.5 IC3.30
RA1  (via drill 0.38)
  Top 0.254: 19.68,27.91 IC3.20 19.7,27.06 19.05,26.42 v17.91,26.42
  Bottom 0.254: v17.91,26.42 17.14,25.65 5.97,25.65 4.45,27.18 J4.8
RA2  (via drill 0.38)
  Top 0.254: IC3.21 18.9,28.73 18.41,29.21 16.64,29.21 16.13,28.7 16.13,27.56 v16.51,27.18
  Bottom 0.254: v16.51,27.18 15.49,26.16 7.24,26.16 4.95,28.45 3.05,28.45 J5.8
RA3  (via drill 0.38)
  Top 0.254: IC3.22 17.31,27.9 v17.02,28.19
  Bottom 0.254: v17.02,28.19 16.26,28.19 14.73,26.67 7.49,26.67 4.45,29.72 J4.9
RA5  (via drill 0.38)
  Top 0.254: IC3.24 17.42,25.3 17.42,25.25 v17.78,24.89
  Bottom 0.254: v17.78,24.89 17.53,25.15 5.71,25.15 4.95,25.91 3.05,25.91 J5.7
RB0  (via drill 0.38)
  Top 0.254: IC3.8 24.18,23.7 v23.11,24.77
  Bottom 0.254: v23.11,24.77 23.49,24.38 25.53,24.38 26.29,25.15 26.29,26.92 24.89,28.32 22.73,28.32 18.29,32.77 15.37,32.77 11.56,36.58 11.56,49.66 JP2.3
RB1  (via drill 0.38)
  Top 0.254: IC3.9 25.03,24.5 v24.26,25.27
  Bottom 0.254: v24.26,25.27 25.27,25.27 25.78,25.78 25.78,26.67 24.64,27.81 22.48,27.81 18.03,32.26 15.11,32.26 11.05,36.32 11.05,48.39 JP1.3
RB2  (via drill 0.38)
  Top 0.254: IC3.10 26.77,25.3 26.54,25.53 26.54,26.54 27.18,27.18 v27.18,27.43
  Bottom 0.254: v27.18,27.43 26.54,27.43 25.15,28.83 22.99,28.83 18.54,33.27 15.62,33.27 12.07,36.83 12.07,47.62 JP3.3
RB3  (via drill 0.38)
  Top 0.254: IC3.11 27.9,26.75 v28.57,27.43
  Bottom 0.254: v28.57,27.43 27.69,28.32 26.42,28.32 25.4,29.34 23.24,29.34 18.8,33.78 15.88,33.78 12.57,37.08 12.57,47.24 13.97,48.64 15.62,48.64 JP4.3
RB4  (via drill 0.38)
  Top 0.254: IC3.14 24.5,26.68 v24.89,26.29
  Bottom 0.254: v24.89,26.29 23.88,27.3 22.22,27.3 17.78,31.75 14.86,31.75 9.27,37.34 9.27,44.58 6.86,46.99 JP5.3
RB5  (via drill 0.38)
  Top 0.254: IC3.15 23.7,26.47 23.67,26.47 v23.62,26.42
  Bottom 0.254: v23.62,26.42 23.24,26.8 21.97,26.8 17.53,31.24 14.61,31.24 8.76,37.08 8.76,42.55 6.86,44.45 JP6.3
RB6  (via drill 0.38)
  Top 0.254: v24.38,17.78 21.46,20.7 21.46,24.38 22.35,25.27 v22.35,25.91 22.35,26.42 22.9,26.96 IC3.16
  Bottom 0.254: v24.38,17.78 24.89,17.27 27.18,17.27 27.94,18.03 32.51,18.03 36.96,22.48 40.89,22.48 44.2,25.78 52.07,25.78 52.58,26.29 52.58,27.18 53.34,27.94 53.34,32.64 53.72,33.02 53.72,34.67 J8.5 | v22.35,25.91 22.1,25.91 17.27,30.73 14.35,30.73 8.25,36.83 8.25,40.51 6.86,41.91 JP7.3
RB7  (via drill 0.38)
  Top 0.254: v23.11,17.78 20.95,19.94 20.95,25.27 v21.21,25.53 21.21,26.04 22.1,26.92 IC3.17
  Bottom 0.254: v23.11,17.78 24.13,16.76 27.43,16.76 28.19,17.53 32.77,17.53 37.21,21.97 41.15,21.97 44.32,25.15 52.2,25.15 53.09,26.04 53.09,26.92 53.85,27.69 53.85,32.26 J8.4 | v21.21,25.53 21.21,26.04 17.02,30.23 14.1,30.23 6.86,37.47 JP8.3
RC0  (via drill 0.38)
  Top 0.254: IC3.32 15.14,18.9 14.61,19.43 13.08,19.43 11.81,18.16 11.68,18.03 10.16,16.51 v9.65,16.51
  Bottom 0.254: v9.65,16.51 9.52,16.64 8.76,17.4 4.7,17.4 J4.4
RC2  (via drill 0.38)
  Top 0.254: IC3.36 19.7,17.67 v20.32,18.29 | v30.99,16.64 R14.2
  Bottom 0.254: J5.3 3.05,15.75 5.08,15.75 5.59,16.26 8.38,16.26 9.14,15.49 10.29,15.49 11.05,16.26 14.48,16.26 14.99,16.76 18.8,16.76 v20.32,18.29 20.7,18.67 21.72,18.67 22.22,18.16 22.22,17.02 22.99,16.26 27.69,16.26 28.19,16.76 30.86,16.76 v30.99,16.64
RC6  (via drill 0.38)
  Top 0.254: v26.92,14.73 26.67,14.73 26.1,15.3 IC3.44
  Bottom 0.254: v26.92,14.73 26.67,14.99 23.62,14.99 22.61,13.97 21.59,13.97 20.83,14.73 16.13,14.73 13.72,12.32 11.05,12.32 9.4,10.67 3.05,10.67 J5.1
RC7  (via drill 0.38)
  Top 0.254: 27.88,18.1 IC3.1 27.83,18.03 28.57,18.03 v28.57,15.88 | v11.94,14.86 11.94,14.1 | 11.94,14.1 10.71,14.1 R12.2 | 11.94,14.1 13.17,14.1 R17.1
  Bottom 0.254: v28.57,15.88 28.45,15.75 15.62,15.75 14.73,14.86 v11.94,14.86 10.29,13.21 3.05,13.21 J5.2
RD0  (via drill 0.38)
  Top 0.254: IC3.38 21.3,17.74 v21.34,17.78
  Bottom 0.254: v21.34,17.78 19.81,16.26 15.37,16.26 14.86,15.75 11.3,15.75 10.54,14.99 8.89,14.99 8.13,15.75 5.97,15.75 4.7,14.48 J4.3
RD1  (via drill 0.38)
  Top 0.254: v22.1,14.86 IC3.39
  Bottom 0.254: v22.1,14.86 21.72,15.24 15.88,15.24 13.46,12.83 10.8,12.83 9.91,11.94 J4.2
REF_RA0  (via drill 0.38)
  Top 0.254: IC1.P$17 29.46,40.65 v30.35,39.75 | 34.8,29.46 v40.77,29.46 | v47.37,39.5 46.99,39.5 45.85,40.64 IC2.P$17 | v18.8,25.53 19.05,25.53 20.5,26.97 IC3.19 20.5,28.88 20.83,29.21 23.49,29.21 v24.51,30.23 | v27.81,30.86 29.08,29.59 29.84,29.59 30.73,28.7 31.5,28.7 31.88,29.08 33.02,29.08 33.4,29.46 34.8,29.46 | 34.8,29.46 v34.8,28.32 | TP3.1 10.49,30.99 R11.2
  Bottom 0.254: v30.35,39.75 34.04,39.75 35.18,38.61 35.18,28.7 v34.8,28.32 | v40.77,29.46 43.56,29.46 46.86,32.77 46.86,38.99 v47.37,39.5 | v18.8,25.53 18.8,27.69 17.4,29.08 16.38,29.08 14.48,27.18 11.68,27.18 | 11.68,27.18 7.75,27.18 5.97,28.96 5.97,29.97 4.95,30.99 3.05,30.99 J5.9 | v24.51,30.23 27.18,30.23 v27.81,30.86 | TP3.1 10.41,30.99 11.81,29.59 11.81,27.3 11.68,27.18
SLEEP_1
  Top 0.254: IC1.P$14 27.41,38.12 27.56,37.97 29.08,37.97 30.1,36.96 30.99,36.96 R9.2
SLEEP_2
  Top 0.254: IC2.P$14 44.7,37.97 45.59,37.97 46.61,36.96 47.5,36.96 R10.2
STEP_1  (via drill 0.38)
  Top 0.254: v30.99,21.46 29.84,20.32 28.96,20.32 28.78,20.5 IC3.4 | IC1.P$16 29.07,40.15 29.34,39.88 29.34,39.37 29.97,38.73 v31.24,38.73
  Bottom 0.254: v31.24,38.73 32.77,38.73 33.15,39.12 33.91,39.12 34.67,38.35 34.67,29.34 33.91,28.57 33.91,27.94 35.05,26.8 35.05,25.15 31.37,21.46 v30.99,21.46 30.86,21.46 30.23,22.1 27.69,22.1 27.3,21.72 19.3,21.72 18.92,22.1 17.65,22.1 15.88,20.32 8,20.32 4.95,23.37 3.05,23.37 J5.6
STEP_2  (via drill 0.38)
  Top 0.254: v49.02,38.61 47.12,38.61 45.58,40.15 IC2.P$16 | IC3.2 26.64,18.9 v26.42,18.67
  Bottom 0.254: v49.02,38.61 47.88,37.47 47.88,32.26 39.88,24.26 37.21,24.26 32,19.05 26.8,19.05 v26.42,18.67 25.53,18.67 25.02,19.18 22.86,19.18 22.35,19.68 19.3,19.68 17.91,18.29 3.05,18.29 J5.4
USB_LED  (via drill 0.38)
  Top 0.254: IC3.41 23.7,13.39 24.51,12.57 25.02,12.57 v25.91,11.68 | R26.2 v33.15,3.05
  Bottom 0.254: v25.91,11.68 30.86,11.68 32.26,10.29 32.26,3.94 v33.15,3.05
USR_LED  (via drill 0.38)
  Top 0.254: IC3.40 22.9,13.42 v24.64,11.68 | v21.21,4.32 21.21,3.09 R25.2
  Bottom 0.254: v24.64,11.68 21.21,8.25 v21.21,4.32
V+  (via drill 0.38, 0.6, 0.8)
  Top 0.254: v38.35,33.53 C6.2 | 24.41,44.96 C7.1 | 27.41,44.96 C8.1 | R13.1 34.38,15.33 36.45,17.4 40.51,17.4 41.15,18.03 41.15,18.29 D1.C 41.15,19.43 | C5.2 22.1,35.18 20.83,33.91 v19.81,33.91 | IC5.3 12.19,44.07 11.3,44.96 C21.2
  Top 0.305: IC1.P$28 24.41,44.96 24.41,45.7 v23.88,46.23 | IC1.P$22 27.41,44.96 27.41,45.7 v27.94,46.23 | 40.92,44.96 40.92,45.7 v40.39,46.23 | 40.92,44.96 IC2.P$28 | 40.92,44.96 C11.1 | 43.92,44.96 43.92,45.57 v44.58,46.23 | 43.92,44.96 IC2.P$22 | 43.92,44.96 C12.1
  Top 0.406: v30.61,47.5 30.1,47.5 28.83,46.23 v27.94,46.23 | v40.39,46.23 39.5,46.23 38.23,47.5 v37.59,47.5 | 41.15,18.29 41.15,18.82
  Top 0.61: IC5.3 13.44,42.14 v13.84,42.55
  Top 0.813: v38.61,27.3 38.73,27.18 C14.+ 42.42,26.05 42.42,20.7 41.15,19.43 | 41.15,18.82 D3.A
  Bottom 0.254: v19.81,33.91 19.43,33.91 19.05,34.29 16.13,34.29 13.08,37.34 13.08,41.78 v13.84,42.55 | 38.23,33.53 v38.35,33.53
  Bottom 0.406: v27.94,46.23 v23.88,46.23 | v40.39,46.23 v44.58,46.23
  Bottom 0.61: v37.59,47.5 34.54,47.5 v30.61,47.5 28.32,49.78 19.18,49.78 13.84,44.45 v13.84,42.55
  Bottom 0.813: 34.54,47.5 34.54,46.1 38.23,42.42 38.23,33.53 38.23,27.69 v38.61,27.3
VBUS  (via drill 0.38)
  Top 0.254: J3.VBUS 12.88,8.18 | R12.1 10.67,10.41 12.01,9.07 12.88,9.07 12.88,8.18 | 12.88,8.18 12.83,8.13 | 38.12,18.82 D2.A 38.59,18.8 38.23,18.8
  Top 0.406: 12.83,8.13 v11.81,8.13 | v35.31,17.53 35.81,18.03 37.47,18.03 38.23,18.8
  Bottom 0.406: v11.81,8.13 19.56,8.13 24,12.57 30.35,12.57 v35.31,17.53
VCAP
  Top 0.254: IC3.23 13.53,26.1 C13.A

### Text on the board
Top: schmalzhaus.com/EBB | EiBot | Board
Bottom: 10/20/2010 BPS
tPlace: GND | 5V | GND | 5V | B1 | B0 | B2 | B3 | GND | MOTOR1 | MOTOR2 | B4 | B5 | DIR1 | DIR2 | B6 | B7 | 3.3V | GND | 3.3V | 5V | + | schmalzhaus.com/EBB | CUR | 3.3V | A0 | A3 | ADJ | ICSP | A2 | A1 | A5 | E0 | D6 | D7 | C1 | D5 | RST | D4 | C0 | PRG | C2 | D0 | 10/20/10 | C7 | D1 | C6 | EiBot | J5 | J4 | GND | PWR | Board | v21 | IN | GND | USR | USB | 5-24VDC
bPlace: GND | 5V | GND | 5V | B1 | B0 | B2 | B3 | B5 | B4 | GND | Arm | Pen | MOTOR 1 | MOTOR 2 | B6 | Servos | 3.3V | Cut JP13, bridge JP14 for | B7 | Alt Servo Power to all servos | GND | GND | JP12 | 3.3V | 3.3V | JP13 | EiBotBoard | PGC(RB6) | Version 2.0 | 5V | 5V | PGD(RB7) | A0 | A3 | Released under Creative | ICSP | GND | Commons V3.0 Attribution | A2 | A1 | Licence by SchmalzHaus | 3.3V | A5 | E0 | MCLR | D6 | D7 | Only for bi-polar stepper motors | Use alt servo power for > 2 servos | C1 | D5 | Adjustable current from | D4 | C0 | A per phase | 50mA to 1.25 | C2 | D0 | microsteps/step | Up to 16 | C7 | D1 | Alt RC | C6 | GND | Servo | Current Adj Voltage TP | 0.0V = 46mA | 2.6V=1.35A | Power | IO PINS | J5 | J4 | 4-6V DC | for more information see: | www.schmalzhaus.com/EBB | Center +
